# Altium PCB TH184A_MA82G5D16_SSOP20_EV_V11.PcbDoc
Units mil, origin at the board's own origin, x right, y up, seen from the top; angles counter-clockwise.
Board outline 3155 x 2110 mil, 2 copper layers (Top Layer, Bottom Layer); 51 components, 39 nets, 254 pads, 149 vias.
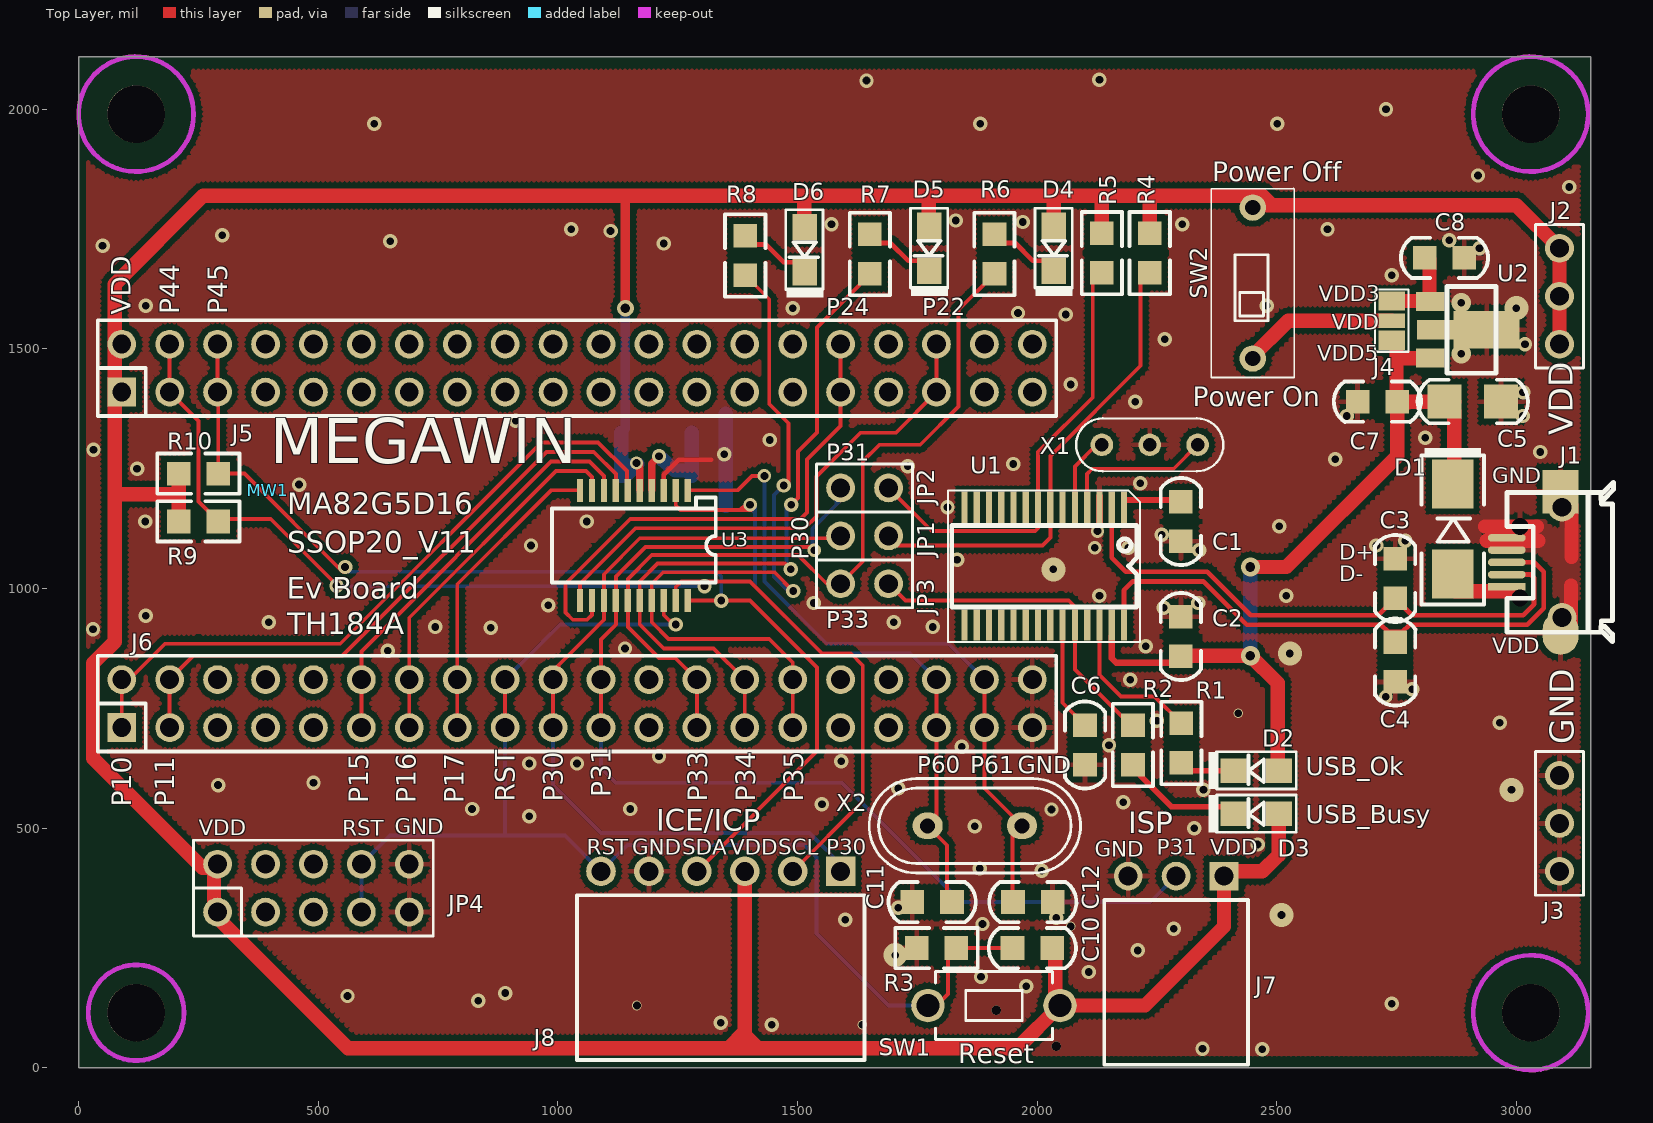
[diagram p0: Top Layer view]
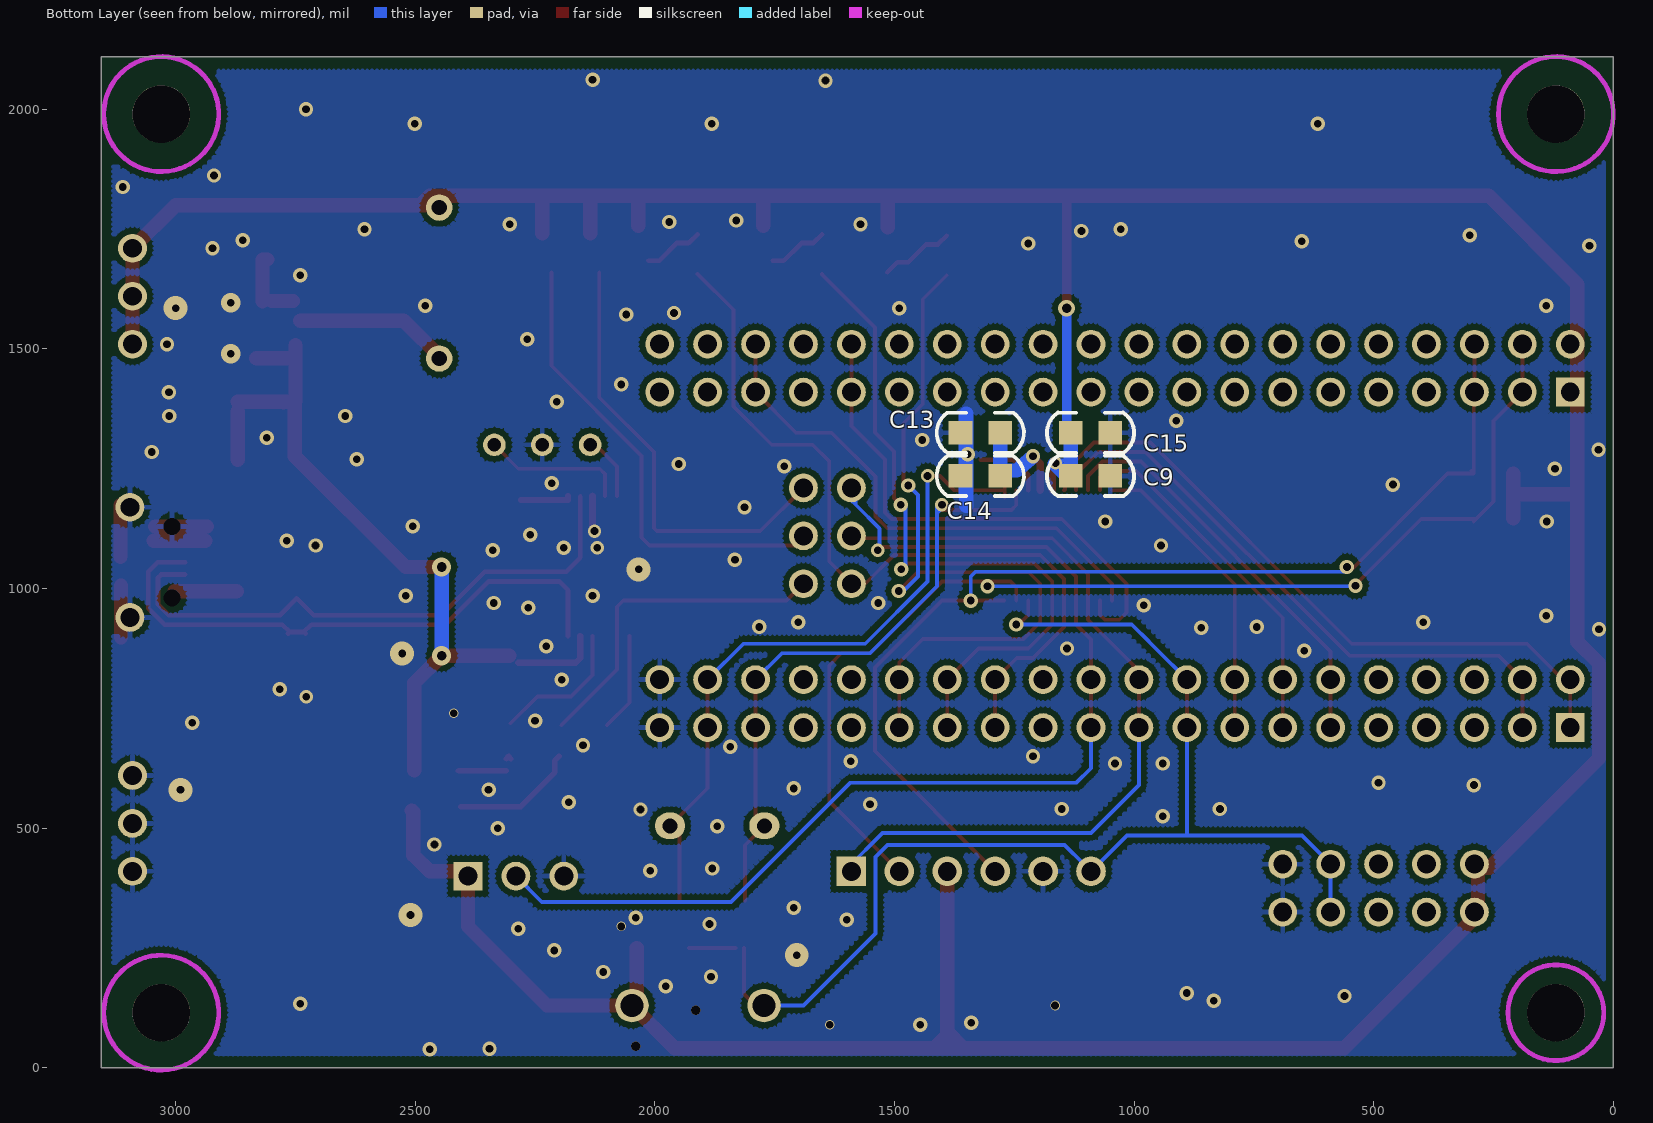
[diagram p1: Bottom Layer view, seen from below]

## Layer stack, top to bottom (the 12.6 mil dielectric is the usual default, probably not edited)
Top Layer: signal copper 1.4
Dielectric: dielectric 12.6, FR-4, Dk 4.8
Bottom Layer: signal copper 1.4

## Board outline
0,0 0,2110 3155,2110 3155,0

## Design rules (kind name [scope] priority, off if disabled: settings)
Clearance 12 [All] p1 off: gap=12
Clearance 10 [All] p2 off: gap=10
Clearance 6 [All] p3: gap=6
ComponentClearance [All] p1 off: gap=10 collisioncheckmode=3 verticalgap=10 showdistances=FALSE
HoleSize [All] p1: absolutevalues=TRUE maxlimit=500 minlimit=1 maxpercent=80.000 minpercent=20.000
MinimumSolderMaskSliver [All] p1 off: minsoldermaskwidth=10
PolygonConnect VIA [ISVIA] p1: connectstyle=Direct reliefconductorwidth=10 reliefentries=4 polygonreliefangle="90 Angle"
PolygonConnect [All] p2: connectstyle=Relief reliefconductorwidth=10 reliefentries=4 polygonreliefangle="90 Angle"
RoutingVias [All] p1: holewidth=16 width=25 viastyle="Through Hole" minholewidth=16 minwidth=24 maxholewidth=28 maxwidth=50
SilkToSilkClearance [All] p1 off: silktosilkclearance=10
SilkscreenOverComponentPads [All] p1 off: minsilkscreentomaskgap=10
SolderMaskExpansion [All] p1 off: expansion=4
Width [All] p1: maxlimit=200 minlimit=6 preferedwidth=10
23 further rules are at their usual default settings.

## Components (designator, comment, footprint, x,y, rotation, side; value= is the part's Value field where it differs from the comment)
C1 "4.7uF" 0805C 2300,1140 r270 top
C2 "0.1uF" 0805C 2300,900 r270 top
C3 "15pF" 0805C 2747.2,1020.79 r90 top
C4 "15pF" 0805C 2747.2,846.62 r270 top
C5 "4.7uF" 1206C 2909.06,1390 r0 top
C6 "0.1uF" 0805C 2100,673.66 r90 top
C7 "0.1uF" 0805C 2710,1390 r180 top
C8 "4.7uF" 0805C 2850,1690 r0 top
C9 "0.1uF" 0805C 1091,1235 r0 bottom
C10 "1u" 0805C 1990,250 r180 top
C11 "NC" 0805C 1781,346 r180 top
C12 "NC" 0805C 1991,346 r0 top
C13 "4.7uF" 0805C 1321,1325 r0 bottom
C14 "0.1uF" 0805C 1321,1235 r180 bottom
C15 "4.7uF" 0805C 1091,1325 r180 bottom
D1 "1N5817" D5817_SMD_1 2867.2,1124.45 r270 top
D2 "Yellow" 0805D 2456.92,620 r180 top
D3 "Red" 0805D 2456.92,530 r180 top
D4 "Green" 0805D 2035,1710 r270 top
D5 "Red" 0805D 1775,1710 r270 top
D6 "Green" 0805D 1515,1706.92 r270 top
J1 "Micro USB母座" JACK_USB_SMD290X220P065 2980,1054.72 r180 top
J2 "*" PS3P254 3090,1510 r90 top
J3 "*" PS3P254 3090,610 r270 top
J4 "*" JUMP3_SMD 2740,1559 r90 top
J5 "CON40A" PS20X2P254 90,1410 r0 top locked
J6 "CON40A" PS20X2P254 90,710 r0 top locked
J7 "*" PS3P254f_90 2390,400 r180 top
J8 "*" PS6P254F_90 1590,410 r180 top locked
JP1 "JUMPER2" PS2P254 1590,1110 r0 top
JP2 "JUMPER2" PS2P254 1590,1210 r0 top
JP3 "JUMPER2" PS2P254 1590,1010 r0 top
JP4 "HEADER 5X2" PS5X2P254 290,325 r0 top
MW1 "MW-A4" MEGAWIN_T 395,1205 r0 top
R1 "1K" 0805R 2301,677.66 r270 top
R2 "1K" 0805R 2200,673.66 r270 top
R3 "47K" 0805R 1790,250 r0 top
R4 "4.7K" 0805R 2235,1700 r270 top
R5 "4.7K" 0805R 2135,1700 r270 top
R6 "1K" 0805R 1911,1698.08 r90 top
R7 "1K" 0805R 1651,1698.08 r90 top
R8 "1K" 0805R 1391,1695 r90 top
R9 "4.7K" 0805R 250,1140 r180 top
R10 "4.7K" 0805R 250,1240 r180 top
SW1 "SW TACT-SPST" SW_T_2P 1910,130 r180 top locked
SW2 "指撥開關" DIP2_SW 2450,1480.04 r90 top
U1 "MA101_TSSOP28_170P0.65" TSSOP28_170P065 2014.84,1046.85 r180 top
U2 "AIC1734-33(SOT-89)" SOT89 2820,1540 r270 top
U3 "MA82G5D16_SSOP20   150P0.635" SSOP20_150P0635 1158.5,1090 r180 top
X1 "6MHz" X3P 2335,1300 r180 top
X2 "NC" X49U 1870,505 r0 top

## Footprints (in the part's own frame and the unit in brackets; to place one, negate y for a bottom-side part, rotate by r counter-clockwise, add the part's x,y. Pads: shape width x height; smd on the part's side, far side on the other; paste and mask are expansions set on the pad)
0805C [mm]
  rect 1.25x1.25 smd: 1(-1.05,0) 2(1.05,0)
  silkscreen extent -2.31,-1.07 2.31,1.07
0805D [mm]
  rect 1.4x1.3 smd: 1(-1.192,0) 2(1.192,0)
  silkscreen extent -2.12,-1 2.53,0.98
0805R [mm]
  rect 1.25x1.25 smd: 1(-1.05,0) 2(1.05,0)
  silkscreen extent -2.18,-1.07 2.18,1.07
1206C [mm]
  rect 1.8x1.8 smd: 1(-1.5,0) 2(1.5,0)
  silkscreen extent -2.92,-1.15 2.92,1.16
D5817_SMD_1 [mm]
  rect 2.6x2.2 smd: 1(2.39,0) 2(-2.39,0)
  silkscreen extent -4.3,-1.65 4,1.65
DIP2_SW [mm]
  round 1.4 hole 0.8: 1(0,0) 2(8,0)
  silkscreen extent -1.02,-2.2 9.02,2.2
JACK_USB_SMD290X220P065 [mm]
  rect 1.9x1.8 on Mech2: 0(-2.85,-1.15) 0(-2.85,1.15)
  round 0.8 hole 0.9 unplated: 1(-0.7,1.9) 5(-0.7,-1.9)
  rect 2x0.4 smd: 1(0,1.3)
  oval 2x0.4 smd: 2(0,0.65) 3(0,0) 4(0,-0.65) 5(0,-1.3)
  round 1.524 hole 1: 5(-2.931,2.921) 5(-2.931,-2.921)
  oval 1.9x2.3 smd: 5(-2.85,3.75)
  rect 1.9x2.3 smd: 5(-2.85,-3.75)
  silkscreen extent -5.65,-4.25 -0.01,4.2
JUMP3_SMD [mil]
  rect 40x55 smd: 1(-41,0) 3(41,0)
  rect 30x55 smd: 2(0,0)
  silkscreen extent -65,-35 65,35
MEGAWIN_T [mil]
PS2P254 [mil]
  round 60 hole 39.37: 1(0,0) 2(100,0)
  silkscreen extent -50,-50 150,50
PS3P254 [mil]
  round 60 hole 39.37: 1(0,0) 2(100,0) 3(200,0)
  silkscreen extent -50,-50 250,50
PS3P254f_90 [mil]
  rect 60x60 hole 39.37: 1(0,0)
  round 60 hole 39.37: 2(100,0) 3(200,0)
  silkscreen extent -50,50 250,394
PS5X2P254 [mil]
  round 60 hole 39.37: 1(0,0) 2(0,100) 3(100,0) 4(100,100) 5(200,0) 6(200,100) 7(300,0) 8(300,100) 9(400,0) 10(400,100)
  silkscreen extent -50,-50 450,150
PS6P254F_90 [mil]
  rect 62x62 hole 39.37: 1(0,0)
  round 62 hole 39.37: 2(100,0) 3(200,0) 4(300,0) 5(400,0) 6(500,0)
  silkscreen extent -50,50 550,394
PS20X2P254 [mil]
  rect 60x60 hole 39.37: 1(0,0)
  round 60 hole 39.37: 2(0,100) 3(100,0) 4(100,100) 5(200,0) 6(200,100) 7(300,0) 8(300,100) 9(400,0) 10(400,100) 11(500,0) 12(500,100) 13(600,0) 14(600,100) 15(700,0) 16(700,100) 17(800,0) 18(800,100) 19(900,0) 20(900,100) 21(1000,0) 22(1000,100) 23(1100,0) 24(1100,100) 25(1200,0) 26(1200,100) 27(1300,0) 28(1300,100) 29(1400,0) 30(1400,100) 31(1500,0) 32(1500,100) 33(1600,0) 34(1600,100) 35(1700,0) 36(1700,100) 37(1800,0) 38(1800,100) 39(1900,0) 40(1900,100)
  silkscreen extent -50,-50 1950,150
SOT89 [mm]
  rect 1.016x1.5 smd: 1(-1.5,0) 3(1.5,0)
  rect 2x3.5 smd: 2(0,3)
  rect 1.016x2.6 smd: 2(0,0.6)
  silkscreen extent -2.3,0.9 2.3,3.5
SSOP20_150P0635 [mil]
  rect 13x48 smd: 1(-112.5,-115) 2(-87.5,-115) 3(-62.5,-115) 4(-37.5,-115) 5(-12.5,-115) 6(12.5,-115) 7(37.5,-115) 8(62.5,-115) 9(87.5,-115) 10(112.5,-115) 11(112.5,115) 12(87.5,115) 13(62.5,115) 14(37.5,115) 15(12.5,115) 16(-12.5,115) 17(-37.5,115) 18(-62.5,115) 19(-87.5,115) 20(-112.5,115)
  silkscreen extent -171,-100 171,77
SW_T_2P [mil]
  round 70 hole 47.24: 1(-137.79,0) 2(137.79,0)
  silkscreen extent -122,-71 122,71
TSSOP28_170P065 [mil]
  rect 13x65 smd: 1(-166.34,-123) 2(-140.75,-123) 3(-115.16,-123) 4(-89.57,-123) 5(-63.98,-123) 6(-38.39,-123) 7(-12.8,-123) 8(12.8,-123) 9(38.39,-123) 10(63.98,-123) 11(89.57,-123) 12(115.16,-123) 13(140.75,-123) 14(166.34,-123) 15(166.34,123) 16(140.75,123) 17(115.16,123) 18(89.57,123) 19(63.98,123) 20(38.39,123) 21(12.8,123) 22(-12.8,123) 23(-38.39,123) 24(-63.98,123) 25(-89.57,123) 26(-115.16,123) 27(-140.75,123) 28(-166.34,123)
  silkscreen extent -200,-158 201,158
X3P [mm]
  round 1.2 hole 0.711: 1(0,0) 2(5.08,0) 3(2.54,0)
  silkscreen extent -1.36,-1.4 6.44,1.4
X49U [mm]
  oval 1.6x1.397 hole 0.8: 1(-2.5,0) 2(2.5,0)
  silkscreen extent -5.6,-2.5 5.6,2.5

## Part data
C1 C5 C8 C13 C15: library part CAP
C2 C3 C4 C6 C7 C9 C14: library part "CAP NP"
C10: library part C
C11 C12: library part "C NP"
D1: library part DIODE_ZD, "Schottky Diode"
D2 D3 D4 D5 D6: library part LED
J1: library part CON5, "Connector"
J2 J3 J4 J7: library part CON3
J8: library part CON6
R1 R2 R4 R5 R6 R7 R8: library part R_Dup1
R3 R9 R10: library part R
SW2: library part "SW SPST"
U1: library part MA101_TSSOP28
U2: library part AIC1734-33(SOT-89)_0
U3: library part MG82FG5Dxx_SSOP-20
X1: library part CRYSTAL_RC
X2: library part CRYSTAL

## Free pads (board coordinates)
  round 120 hole 120 unplated: 0(120,115) 0(120,1990) 0(3030,115) 0(3030,1990)

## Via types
v1: diameter 30, hole 16, Top Layer to Bottom Layer, tented both sides, 125 vias
v2: diameter 28, hole 16, Top Layer to Bottom Layer, tented both sides, 7 vias
v3: diameter 50, hole 16, Top Layer to Bottom Layer, tented both sides, 6 vias
v4: diameter 20, hole 16, Top Layer to Bottom Layer, tented both sides, 4 vias
v5: diameter 40, hole 20, Top Layer to Bottom Layer, tented both sides, 2 vias
v6: diameter 20, hole 20, Top Layer to Bottom Layer, tented both sides, 2 vias
v7: diameter 40, hole 16, Top Layer to Bottom Layer, tented both sides, 2 vias
v8: diameter 35, hole 20, Top Layer to Bottom Layer, tented both sides, 1 vias

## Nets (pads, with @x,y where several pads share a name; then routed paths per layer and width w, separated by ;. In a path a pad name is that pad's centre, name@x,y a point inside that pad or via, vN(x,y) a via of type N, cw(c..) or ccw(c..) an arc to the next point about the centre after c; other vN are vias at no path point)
D+: C4.1 J1.3 U1.28 | length 1213
  Top Layer w10: U1.28@2181.18,901.18 2181.18,996.18 2200,1015 2346.72,1015 2437.27,924.45 2717.2,924.45 C4.1@2732.2,909.45 ; C4.1@2728.96,906.21 C4.1@2732.2,909.45 ; C4.1@2765.45,906.21 C4.1@2762.2,909.45 ; J1.3 3036.93,1054.72 3057,1034.65 3057,959 3022.45,924.45 2777.2,924.45 C4.1@2762.2,909.45 ; C4.1@2732.2,909.45 C4.1@2762.2,909.45
D-: C3.1 J1.2 U1.2 | length 1212.7
  Top Layer w10: U1.2@2155.59,1192.52 U1.2 2155.59,1064.41 2185,1035 2355,1035 2445.55,944.45 2712.2,944.45 C3.1 2782.2,944.45 3014.16,944.45 3037,967.28 3037,1022.57 3030.43,1029.13 J1.2
GND_POWER: C1.2 C2.1 C3.2 C4.2 C5.2 C6.1 C7.2 C8.2 C9.1 C11.2 C12.2 C13.2 C14.1 C15.2 J1.4 J1.5 J3.1 J3.2 J3.3 J6.39 J6.40 J7.3 J8.5 JP4.9 JP4.10 R3.1 U1.3 U2.2 U3.3 X1.3 | length 834.4
  Top Layer w10: U3.3 1221,1237.58 1252.42,1269 1320,1269
  Top Layer w15: v2@2130,1126 U1.3@2130,1192.52
  Top Layer w30: 2934.48,1129.53 3007.56,1129.53 3042.28,1129.53 ; 2938.2,1100 3007.56,1100 3046,1100 ; J1.5@3114,898 3114,939.72 3114,1005.8 ; 3115,1066.2 J1.5@3115,1174
  Bottom Layer w30: 1350,1172.93 1350,1365
  other v1: 2470,39 2345,40 1446,90 1340,94 2740,134 834,140 561,150 890,156 1977,170 1883,190 2108,200 2210,245 2285,290 1886,300 1600,309 2040,313 1710,334 2010,411 1880,416 2460,466 2328,500 1870,504 940,525 2030,539 821,540 1151,540 1551,550 2180,554 2347,580 1710,583 291,590 490,595 940,635 1040,635 1591,640 1211,650 1843,670 2150,673 2965,720 2250,724 2783,790 2194,810 645,870 1140,875 2227,880 30,915 860,918 744,920 1782,920 397,930 1701,930 140,943 2264,960 980,965 1534,970 2336,970 2130,985 2520,985 1833,1060 2338,1080 2190,1085 944,1090 2708,1090 2768,1100 2260,1112 2505,1130 139,1140 1060,1140 1813,1170 460,1217 2215,1220 122,1250 1730,1255 1950,1260 2622,1270 1347,1280 3050,1285 31,1290 1442,1310 2810,1315 912,1350 2646,1360 3013,1360 2205,1390 3014,1410 2070,1426 3018,1510 2266,1520 2060,1572 1960,1575 1490,1585 140,1590 2479,1590.04 2740,1654 2923,1710 50,1715 1221,1720 650,1725 2860,1727 300,1737 1110,1746 1028,1750 2606,1750 1571,1760 2303,1760 1970,1765 1830,1768 3110,1838 2920,1862 617,1970 1881,1970 2501,1970 2728,2000 1644,2060 2130,2062
  other v2: 2727.2,774.45 2120,1085 2126,1120
  other v3: 1704,235 2510,319 2990,580 2527.2,864.45 2034,1040 3000,1585
  other v4: 1635,90 1165,130 2070,295 2420,740
  other v6: 2040,45 1915,120
  other v7: 2885,1490 2885,1596.37
MA101_RX: JP2.2 R5.2 U1.8 | length 933
  Top Layer w8: JP2.2 1780,1120 1996,1120 2002.05,1126.05 U1.8 2002.05,1285.04 2116,1398.99 R5.2@2116,1660
MA101_TX: JP1.2 R4.2 U1.7 | length 984.2
  Top Layer w8: JP1.2 1710,1090 2011,1090 2027.64,1106.64 U1.7 2027.64,1276.64 2216,1465 R4.2@2216,1660
NetC1_1: C1.1 U1.1 | length 105
  Top Layer w13: U1.1@2181.18,1192.52 2181.18,1185 C1.1@2278.66,1185
NetC6_2: C6.2 U1.23 | length 205.6
  Top Layer w8: U1.23@2053.23,901.18 2053.23,761.77 C6.2
NetC13_1: C13.1 C14.2 U3.4 | length 249.8
  Top Layer w8: U3.4 U3.4@1198,1207
  Top Layer w15: U3.4 1196,1261 v1(1211,1276)
  Bottom Layer w30: v1(1211,1276) 1245.15,1246.33 C14.2@1279.66,1246.33 ; C14.2 C14.2@1279.66,1246.33 ; C13.1 C14.2@1279.66,1246.33
NetD1_1: D1.1 J1.1 | length 130
  Top Layer w30: D1.1@2872.2,994.45 J1.1@3002.2,994.45
NetD2_2: D2.2 R1.2 | length 107.2
  Top Layer w12: R1.2@2300.6,645 R1.2@2301,645 ; R1.2@2305,650 R1.2@2309.84,645.16 ; R1.2@2310,620 D2.2
NetD3_2: D3.2 R2.2 | length 263.1
  Top Layer w12: R2.2@2200,650 2208.84,641.16 2208.84,616.16 2280,545 D3.2@2405,545
NetD4_2: D4.2 R6.2 | length 125.9
  Top Layer w10: R6.2 1929.34,1721.08 1954,1721.08 1991,1684.08 D4.2@2014,1684.08
NetD5_2: D5.2 R7.2 | length 125.9
  Top Layer w10: R7.2 1669.34,1721.08 1694,1721.08 1731,1684.08 D5.2@1754,1684.08
NetD6_2: D6.2 R8.2 | length 155.6
  Top Layer w10: R8.2 1409.34,1718 1434,1718 1471,1681 1494,1681 D6.2
NetJ4_2: J4.2 SW2.1 | length 327.7
  Top Layer w30: SW2.1@2445,1480 2524,1559 J4.2
NetU1_4: U1.4 X1.1 | length 302.6
  Top Layer w8: U1.4@2104.41,1192.52 2104.41,1239.41 2115,1250 2285,1250 X1.1
NetU1_5: U1.5 X1.2 | length 137.3
  Top Layer w8: U1.5@2078.82,1192.52 2078.82,1255 2123.82,1300 X1.2
P10: J6.1 J6.2 U3.6 | length 1430.9
  Top Layer w8: J6.1 J6.2@90,795 ; J6.2 J6.2@90,795 ; U3.6 1144,1207 1144,1245 1084,1305 966,1305 546,885 180,885 J6.2@90,795
P11: J6.3 J6.4 U3.7 | length 1260.8
  Top Layer w8: J6.3 J6.4@190,790 ; J6.4 240,860 551,860 976,1285 1075,1285 1121,1239 U3.7
P15: J6.11 J6.12 U3.8 | length 871.5
  Top Layer w8: J6.11 J6.12 590,869 986,1265 1066,1265 1096,1235 U3.8
P16: J6.13 J6.14 U3.9 | length 769.7
  Top Layer w8: J6.13 J6.14 690,939 996,1245 1059,1245 1071,1233 U3.9
P17: J6.15 J6.16 U3.10 | length 636.2
  Top Layer w8: J6.15 J6.16 790,1009 986,1205 U3.10
P22: J5.35 J5.36 U3.11 | length 1093.5
  Top Layer w8: U3.11 1046,1010 1162,1126 1515.28,1126 1540,1150.72 1540,1234 1631,1325 1705,1325 J5.35 J5.36
P24: J5.31 J5.32 U3.12 | length 1137.1
  Top Layer w8: U3.12 1071,945 1061,935 1031,935 1016,950 1016,1010 1151,1145 1506,1145 1520,1159 1520,1269 1590,1339 J5.31 ; J5.31@1570,1410 J5.31 ; J5.31@1590,1394 J5.31 ; J5.32 J5.31
P30/RXD: J6.19 J6.20 J8.1 JP1.1 U3.13 | length 1690
  Top Layer w8: J6.19 J6.20 J6.20@990,814 ; J6.20@990,829 1001,840 ; J6.20@1001,825 1001,840 ; JP1.1 1585,1105 1171,1105 1096,1030 U3.13 1096,935 1001,840
  Bottom Layer w8: J6.19 990,590 1090,490 1525,490 J8.1@1597.5,417.5
P31/TXD: J6.21 J6.22 J7.2 JP2.1 U3.14 | length 2358
  Top Layer w8: J6.21 J6.22 1090,894 1121,925 U3.14 1121,1025 1183,1087 1532,1087 1535,1090 1537,1090 1535,1088 v2(1535,1080)
  Bottom Layer w8: J6.21 1090,625 1120,595 1592,595 1841,346 2236,346 J7.2 ; v2@1531,1081 1531,1125 1581,1175 ; JP2.1@1581,1201 1581,1175 ; JP2.1@1590,1184 1581,1175
P33: J6.25 J6.26 JP3.1 R6.1 U3.15 | length 1779.6
  Top Layer w8: J6.26@1290,795 J6.25 J6.26 1245,855 1211,855 1146,920 U3.15 1146,1020 1196,1070 1501,1070 1561,1010 JP3.1@1576,1010 ; JP3.1 1636,1056 1636,1265 1671,1300 1756,1300 1836,1380 1836,1581.74 R6.1
P34: J6.27 J6.28 R7.1 U3.16 | length 1462.6
  Top Layer w8: J6.27 J6.28@1390,795 ; J6.28 1325,875 1221,875 1171,925 U3.16 1171,1015 1208,1052 1474,1052 v1(1486,1040) ; v1(1487,1175) 1501,1189 1501,1286 1541,1326 1541,1545 1651,1655 R7.1
  Bottom Layer w8: v1@1477,1039 v1@1477,1175
P35: J6.29 J6.30 R8.1 U3.17 | length 1599.9
  Top Layer w8: R8.1 1441,1603.66 1441,1385 1481,1345 1481,1214 v1@1476.5,1209.5 ; J6.29 J6.30 1490,846 1441,895 1231,895 1196,930 U3.17 1196,1010 1220,1034 1452,1034 v1(1491,995)
  Bottom Layer w8: v1(1471,1215) 1451,1195 1451,1025 1481,995 v1(1491,995)
P44: J5.3 J5.4 J8.2 R9.1 U3.19 | length 2640
  Top Layer w8: J5.3@190,1411 J5.3 ; J5.4 J5.3 ; 250,1298 250,1181.34 ; R9.1 R9.1@286.34,1145 ; v1@538,1008 401,1145 R9.1@286.34,1145 ; U3.19 1246,1003 1258,1015 1401,1015 1551,865 1611,865 1636,840 1636,825 ; J8.2 1636,556 1636,825 ; 1636,795 1636,825 ; J5.3 250,1350 250,1181.34 ; 250,1181.34 R9.1@286.34,1145
  Bottom Layer w8: v1@545,1005 v1(1306,1005) ; J8.2 J8.2@1490,430 ; J8.2@1510,410 J8.2@1510,415
  other v1: 538,1006
P45: J5.5 J5.6 J8.4 R10.1 U3.20 | length 2354.2
  Top Layer w8: J5.6 J5.5 ; 291.34,1301.34 291.34,1285 ; J5.5@295,1410 J5.5 ; R10.1@296.34,1245 R10.1@291.34,1250 ; v1@556,1035 551,1035 346,1240 R10.1 R10.1@291.34,1250 ; U3.20 v1(1341,975) 1401,975 1541,835 1541,661 J8.4 ; J5.5 284.5,1404.5 291.34,1397.65 291.34,1285 ; R10.1@291.34,1250 291.34,1285
  Bottom Layer w8: J5.5 J5.5@295,1410 ; v1@556,1035 1331,1035 1341,1025 v1(1341,975)
  other v1: 556,1045
P60: C11.1 J6.35 J6.36 U3.2 X2.1 | length 1339.4
  Top Layer w8: U3.2 1246,1174 1256,1164 1380,1164 ; v2@1392,1176 1380,1164 ; v2@1403,1164 1380,1164 ; J6.36@1772,809 J6.36@1772,810 ; J6.36 J6.35 1790,523.42 X2.1 1812,464.58 C11.1@1812,349
  Bottom Layer w8: v2@1401,1168 1411,1158 ; v2@1411,1175 1411,1158 ; J6.36 1735,865 1551,865 1411,1005 1411,1158
  other v2: 1401,1175
P61: C12.1 J6.37 J6.38 U3.1 X2.2 | length 1477.2
  Top Layer w8: U3.1@1270,1190 U3.1@1270,1205 ; U3.1@1270,1220 U3.1@1270,1205 ; v2(1431,1235) 1405,1235 1375,1205 U3.1 U3.1@1270,1205 ; v2@1431,1240 v2@1436,1240 ; J6.38 J6.37 1890,583.42 X2.2 1948.66,485.24 C12.1@1948.66,350
  Bottom Layer w8: v2@1441,1235 1431,1225 1431,1015 1561,885 1815,885 J6.38
RST: C10.2 J6.17 J6.18 J8.6 JP4.7 JP4.8 R3.2 SW1.2 U3.18 | length 2659.7
  Top Layer w8: J6.17 J6.18 ; J8.6 J8.6@1090,426 ; U3.18 1221,945 v1@1241,925 ; SW1.2 1790,130 1814,154 R3.2@1814,250 ; R3.2 C10.2@1928.66,250
  Bottom Layer w8: JP4.7 JP4.8 650,485 890,485 ; J6.17 890,485 ; J6.18 953.5,873.5 ; 985,905 953.5,873.5 ; J8.6 1015,485 890,485 ; J8.6@1105,425 1145,465 1515,465 1540,440 1540,280 1690,130 SW1.2 ; v1@1241,925 1005,925 953.5,873.5
  other v1: 1246,925
USB_BUSY: JP3.2 R2.1 U1.24 | length 703.9
  Top Layer w8: JP3.2 1725,975 2066,975 2078.82,962.18 U1.24 2078.82,831.18 R2.1@2195,715
USB_OK: R1.1 U1.26 | length 294
  Top Layer w8: U1.26@2130,901.18 2130,820 2175,775 2245,775 R1.1
VDD: C9.2 C10.1 C15.1 D3.1 D4.1 D5.1 D6.1 J2.1 J2.2 J2.3 J5.1 J5.2 J7.1 J8.3 JP4.1 JP4.2 R4.1 R5.1 R9.2 R10.2 SW1.1 SW2.2 U3.5 | length 9743.6
  Top Layer w15: U3.5 v2@1171,1262
  Top Layer w20: v8(1141,1585) 1141,1820
  Top Layer w30: 75.09,1140 75.09,889.09 ; 75.09,1240 75.09,1197 ; R9.2@208.66,1147 208.66,1197 ; R10.2 208.66,1197 ; J8.3 1390,75 ; D6.1@1514,1753.84 1514,1806.92 ; D5.1@1774,1756.92 1774,1810 ; D4.1 2035,1810 ; SW1.1@2037.79,130 C10.1@2037.79,250 ; R5.1 2135,1820 ; R4.1 2235,1815 ; SW2.2@2460,1820 2470,1820 ; 2480,1800 2490,1800 ; D3.1@2506.92,536.92 2503.84,533.84 D3.1 2503.84,443.84 2470,410 2390,410 J7.1 2390,295 2225,130 SW1.1 1958.79,41 1416.79,41 ; 2845,1800 3000,1800 ; J2.1 J2.2 J2.3 3000,1800 ; 75.09,889.09 75.09,1197 ; 75.09,889.09 30,844 30,646 258.5,417.5 282.5,417.5 282.5,320.5 562,41 1356,41 ; 75.09,1197 75.09,1635.09 260,1820 1141,1820 2135,1820 ; 75.09,1197 208.66,1197 ; 1356,41 1390,75 ; 1356,41 1390,41 ; 1390,41 1416.79,41 ; 1390,41 1390,67.79 ; 1390,67.79 1416.79,41 ; 1390,67.79 1390,75 ; 2135,1820 2470,1820 ; 2470,1820 2490,1800 ; 2490,1800 3000,1800
  Bottom Layer w8: 1132,1267 1132.34,1267 v2@1158,1267
  Bottom Layer w20: C15.1 1141,1333.66 v8(1141,1585)
  Bottom Layer w30: C9.2 1132.34,1267 C15.1 ; C9.2@1141,1235 v2@1166,1260
  other v2: 1164,1262
VDD3: C8.1 J4.3 U2.1 | length 142.7
  Top Layer w30: J4.3@2755,1600 U2.1@2800,1600 ; C8.1@2808.66,1686.77 2818.66,1686.77 U2.1@2818.66,1599.06
VDD5: C2.2 C5.1 C7.1 D1.2 D2.1 J4.1 U1.27 U2.3 | length 1707
  Top Layer w13: U1.27@2155.59,901.18 2155.59,854.41 2165,845 C2.2@2285,845
  Top Layer w30: C2.2@2303.66,860 v5(2445,860) 2502,803 D2.1@2502,620.66 ; v5(2445,1045) 2520,1045 2751.34,1276.34 C7.1 ; J4.1@2750,1508 2750,1480.94 ; C7.1@2775,1389.06 C7.1@2775,1390 ; U2.3@2831.89,1480.94 U2.3 2750,1480.94 ; D1.2@2870,1269.06 C5.1@2870,1370 ; C5.1@2870,1390 C5.1 C7.1@2775,1390 ; 2750,1480.94 2750,1390 C7.1 ; C7.1 C7.1@2775,1390
  Bottom Layer w30: v5(2445,860) v5(2445,1045)
pads on no net: J1.0 J5.7 J5.8 J5.9 J5.10 J5.11 J5.12 J5.13 J5.14 J5.15 J5.16 J5.17 J5.18 J5.19 J5.20 J5.21 J5.22 J5.23 J5.24 J5.25 J5.26 J5.27 J5.28 J5.29 J5.30 J5.33 J5.34 J5.37 J5.38 J5.39 J5.40 J6.5 J6.6 J6.7 J6.8 J6.9 J6.10 J6.23 J6.24 J6.31 J6.32 J6.33 J6.34 JP4.3 JP4.4 JP4.5 JP4.6 U1.6 U1.9 U1.10 U1.11 U1.12 U1.13 U1.14 U1.15 U1.16 U1.17 U1.18 U1.19 U1.20 U1.21 U1.22 U1.25

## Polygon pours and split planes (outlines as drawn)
GND_POWER on Top Layer "Bottom Layer-No Net" (hatched 90Degree grid 10 track 10, remove dead copper, pour order 1001): 20,29 3130,29 3130,2080 20,2080
GND_POWER on Bottom Layer "Bottom Layer-No Net" (hatched 90Degree grid 10 track 10, remove dead copper, pour order 1001): 20,29 3130,29 3130,2080 20,2080

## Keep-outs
Keep-Out Layer:
  circle w10: c3030,1990 r120
  circle w10: c120,115 r100
  circle w10: c120,1990 r120
  circle w10: c3030,115 r120

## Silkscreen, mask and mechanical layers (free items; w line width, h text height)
Top Overlay:
  text "Power Off" at 2365,1850.04 h40
  text "VDD3" at 2588,1600 h33
  text "P44" at 210,1572 h40 r90
  text "P45" at 310,1572 h40 r90
  text "VDD" at 109,1571 h40 r90
  text "P24" at 1560,1570 h35
  text "P22" at 1760,1570 h35
  text "VDD" at 2615,1540 h33
  text "VDD5" at 2585,1475 h33
  text "Power On" at 2325,1380 h40
  text "VDD" at 3118,1320 h50 r90
  text "P31" at 1560,1267 h35
  text "GND" at 2950,1220 h33
  text "MA82G5D16" at 435,1155 h45
  text "SSOP20_V11" at 435,1075 h45
  text "P30" at 1523.66,1060 h35 r90
  text "D+" at 2630,1060 h33
  text "D-" at 2630,1015 h33
  text "Ev Board" at 434,979 h45
  text "P33" at 1560,917 h35
  text "TH184A" at 435,905 h45
  text "VDD" at 2950,865 h33
  text "GND" at 3120,675 h50 r90
  text "P60" at 1750,615 h35
  text "P61" at 1860,615 h35.43
  text "GND" at 1960,615 h35.43
  text "USB_Ok" at 2560,610 h38
  text "P31" at 1110,565 h40 r90
  text "RST" at 910,555 h40 r90
  text "P30" at 1010,555 h40 r90
  text "P33" at 1312,555 h40 r90
  text "P34" at 1412,555 h40 r90
  text "P35" at 1512,555 h40 r90
  text "P15" at 603.95,551.95 h40 r90
  text "P16" at 703.95,551.95 h40 r90
  text "P17" at 803.95,551.95 h40 r90
  text "P10" at 110,545 h40 r90
  text "P11" at 200,545 h40 r90
  text "USB_Busy" at 2560,510 h38
  text "ICE/ICP" at 1205,495 h45
  text "ISP" at 2190,490 h45
  text "GND" at 660,487 h33
  text "VDD" at 251,485 h33
  text "RST" at 550,484 h33
  text "RST" at 1060,445 h33
  text "GND" at 1155,445 h33
  text "SDA" at 1260,445 h33
  text "VDD" at 1360,445 h33
  text "SCL" at 1460,445 h33
  text "P30" at 1560,445 h33
  text "P31" at 2250,445 h33
  text "VDD" at 2361,445 h33
  text "GND" at 2120,440 h33
  text "Reset" at 1835,10 h40
Mechanical 1:
  the board outline again, w13
Mechanical 2:
  circle w10: c3030,115 r120
  circle w10: c120,1990 r120
  circle w10: c120,115 r100
  circle w10: c3030,1990 r120

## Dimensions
0,2110 to 0,0 on Top Overlay
0,0 to 3155,0 on Top Overlay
